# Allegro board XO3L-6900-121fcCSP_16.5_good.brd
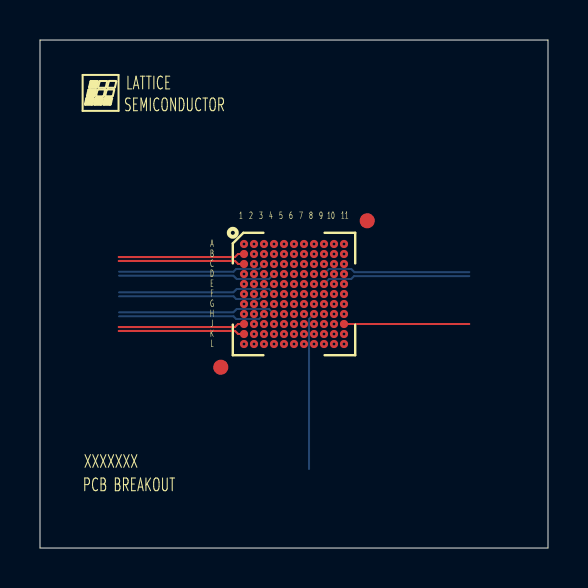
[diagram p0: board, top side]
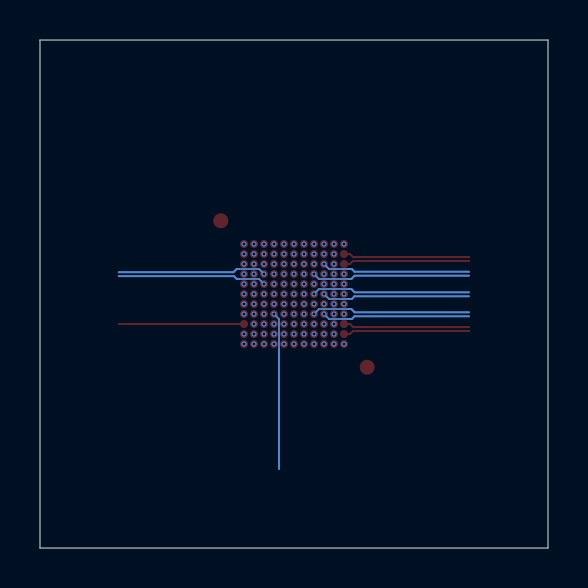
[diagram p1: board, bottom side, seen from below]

Outline 25.4 x 25.4 mm; copper layers: TOP, L2_GND, L3_SIGNAL1, L4_SIGNAL2, L5_PWR, BOTTOM. Coordinates in mm from the lower left corner of the outline.
Outline path: 0,25.4 25.4,25.4 25.4,0 0,0 0,25.4

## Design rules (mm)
net group CDPL10: nets PL10C PL10D
net group CDPT13: nets PT13C PT13D
net group CDPT15: nets PT15C PT15D
net group CDPT20: nets PT20C PT20D
net group CDPT23: nets PT23C PT23D
net group CDPT28: nets PT28C PT28D
net group PB3: nets PB3A PB3B
net group PB4: nets PB4A PB4B
net group PB7: nets PB7A PB7B
net group PB9: nets PB9A PB9B
net group PB10: nets PB10A PB10B
net group PB13: nets PB13A PB13B
net group PB20: nets PB20A PB20B
net group PB21: nets PB21A PB21B
net group PB24: nets PB24A PB24B
net group PB27: nets PB27A PB27B
net group PB29: nets PB29A PB29B
net group PB30: nets PB30A PB30B
net group PL3: nets PL3A PL3B
net group PL4: nets PL4A PL4B
net group PL6: nets PL6A PL6B
net group PL7: nets PL7A PL7B
net group PL8: nets PL8A PL8B
net group PL9: nets PL9A PL9B
net group PL14: nets PL14A PL14B
net group PL16: nets PL16A PL16B
net group PL17: nets PL17A PL17B
net group PL20: nets PL20A PL20B
net group PR2: nets PR2A PR2B
net group PR3: nets PR3A PR3B
net group PR5: nets PR5A PR5B
net group PR6: nets PR6A PR6B
net group PR8: nets PR8A PR8B
net group PR9: nets PR9A PR9B
net group PR10: nets PR10A PR10B
net group PR13: nets PR13A PR13B
net group PR14: nets PR14A PR14B
net group PR15: nets PR15A PR15B
net group PR16: nets PR16A PR16B
net group PR18: nets PR18A PR18B
net group PR19: nets PR19A PR19B
net group PT9: nets PT9A PT9B
net group PT11: nets PT11A PT11B
net group PT14: nets PT14A PT14B
net group PT18: nets PT18A PT18B
net group PT21: nets PT21A PT21B
net group PT24: nets PT24A PT24B
net group PT27: nets PT27A PT27B

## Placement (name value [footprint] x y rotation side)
BGA  -  [BGA121N50P11X11_600X600X100B-1]  12.7 12.7 270 top
NOREF  -  []  1.85 21.54 0 top

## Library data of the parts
BGA = BGA121N50P11X11_600X600X100B-1

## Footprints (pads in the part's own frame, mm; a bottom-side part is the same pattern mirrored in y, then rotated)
BGA121N50P11X11_600X600X100B-1
  round 0.75 smd: (-3.66,3.66) (3.66,-3.66)
  round 0.406 smd: A1(-2.5,-2.5) A2(-2.5,-2) A3(-2.5,-1.5) A4(-2.5,-1) A5(-2.5,-0.5) A6(-2.5,0) A7(-2.5,0.5) A8(-2.5,1) A9(-2.5,1.5) A10(-2.5,2) A11(-2.5,2.5) B1(-2,-2.5) B2(-2,-2) B3(-2,-1.5) B4(-2,-1) B5(-2,-0.5) B6(-2,0) B7(-2,0.5) B8(-2,1) B9(-2,1.5) B10(-2,2) B11(-2,2.5) C1(-1.5,-2.5) C2(-1.5,-2) C3(-1.5,-1.5) C4(-1.5,-1) C5(-1.5,-0.5) C6(-1.5,0) C7(-1.5,0.5) C8(-1.5,1) C9(-1.5,1.5) C10(-1.5,2) C11(-1.5,2.5) D1(-1,-2.5) D2(-1,-2) D3(-1,-1.5) D4(-1,-1) D5(-1,-0.5) D6(-1,0) D7(-1,0.5) D8(-1,1) D9(-1,1.5) D10(-1,2) D11(-1,2.5) E1(-0.5,-2.5) E2(-0.5,-2) E3(-0.5,-1.5) E4(-0.5,-1) E5(-0.5,-0.5) E6(-0.5,0) E7(-0.5,0.5) E8(-0.5,1) E9(-0.5,1.5) E10(-0.5,2) E11(-0.5,2.5) F1(0,-2.5) F2(0,-2) F3(0,-1.5) F4(0,-1) F5(0,-0.5) F6(0,0) F7(0,0.5) F8(0,1) F9(0,1.5) F10(0,2) F11(0,2.5) G1(0.5,-2.5) G2(0.5,-2) G3(0.5,-1.5) G4(0.5,-1) G5(0.5,-0.5) G6(0.5,0) G7(0.5,0.5) G8(0.5,1) G9(0.5,1.5) G10(0.5,2) G11(0.5,2.5) H1(1,-2.5) H2(1,-2) H3(1,-1.5) H4(1,-1) H5(1,-0.5) H6(1,0) H7(1,0.5) H8(1,1) H9(1,1.5) H10(1,2) H11(1,2.5) J1(1.5,-2.5) J2(1.5,-2) J3(1.5,-1.5) J4(1.5,-1) J5(1.5,-0.5) J6(1.5,0) J7(1.5,0.5) J8(1.5,1) J9(1.5,1.5) J10(1.5,2) J11(1.5,2.5) K1(2,-2.5) K2(2,-2) K3(2,-1.5) K4(2,-1) K5(2,-0.5) K6(2,0) K7(2,0.5) K8(2,1) K9(2,1.5) K10(2,2) K11(2,2.5) L1(2.5,-2.5) L2(2.5,-2) L3(2.5,-1.5) L4(2.5,-1) L5(2.5,-0.5) L6(2.5,0) L7(2.5,0.5) L8(2.5,1) L9(2.5,1.5) L10(2.5,2) L11(2.5,2.5)

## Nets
GND: BGA.A1 BGA.A11 BGA.E6 BGA.E7 BGA.F5 BGA.F6 BGA.G5 BGA.G6 BGA.L1 BGA.L11
VCC: BGA.D5 BGA.E5 BGA.F7 BGA.G7
VCCIO0: BGA.D6
VCCIO1: BGA.H5
VCCIO2: BGA.H6
VCCIO3: BGA.H8
VCCIO4: BGA.F8
VCCIO5: BGA.D8
PB3A: BGA.H9
PB3B: BGA.J9
PB4A: BGA.K10
PB4B: BGA.L10
PB7A: BGA.K9
PB7B: BGA.L9
PB9A: BGA.J8
PB9B: BGA.H7
PB10A: BGA.K8
PB10B: BGA.L8
PB13A: BGA.L7
PB13B: BGA.K7
PB15B: BGA.J7
PB20A: BGA.L6
PB20B: BGA.K6
PB21A: BGA.L5
PB21B: BGA.K5
PB23A: BGA.J6
PB24A: BGA.L4
PB24B: BGA.K4
PB27A: BGA.J5
PB27B: BGA.J4
PB29A: BGA.L3
PB29B: BGA.K3
PB30A: BGA.L2
PB30B: BGA.K2
PL3A: BGA.C9
PL3B: BGA.E8
PL4A: BGA.B10
PL4B: BGA.B11
PL6A: BGA.C10
PL6B: BGA.C11
PL7A: BGA.D9
PL7B: BGA.E9
PL8A: BGA.D10
PL8B: BGA.D11
PL9A: BGA.E10
PL9B: BGA.E11
PL10C: BGA.F11
PL10D: BGA.F10
PL13A: BGA.F9
PL14A: BGA.G11
PL14B: BGA.G10
PL16A: BGA.G9
PL16B: BGA.G8
PL17A: BGA.H11
PL17B: BGA.H10
PL19A: BGA.J11
PL20A: BGA.K11
PL20B: BGA.J10
PR2A: BGA.C2
PR2B: BGA.D3
PR3A: BGA.B1
PR3B: BGA.C1
PR5A: BGA.D2
PR5B: BGA.D1
PR6A: BGA.E4
PR6B: BGA.E3
PR8A: BGA.E2
PR8B: BGA.E1
PR9A: BGA.F3
PR9B: BGA.F4
PR10A: BGA.F2
PR10B: BGA.F1
PR13A: BGA.G1
PR13B: BGA.G2
PR14A: BGA.G3
PR14B: BGA.G4
PR15A: BGA.H1
PR15B: BGA.H2
PR16A: BGA.H3
PR16B: BGA.H4
PR18A: BGA.J1
PR18B: BGA.K1
PR19A: BGA.J2
PR19B: BGA.J3
PT9A: BGA.A10
PT9B: BGA.B9
PT10A: BGA.C8
PT11A: BGA.A9
PT11B: BGA.B8
PT13C: BGA.D7
PT13D: BGA.A8
PT14A: BGA.A7
PT14B: BGA.B7
PT15C: BGA.C7
PT15D: BGA.C6
PT18A: BGA.B6
PT18B: BGA.A6
PT20C: BGA.A5
PT20D: BGA.B5
PT21A: BGA.A4
PT21B: BGA.B4
PT23C: BGA.C5
PT23D: BGA.C4
PT24A: BGA.A3
PT24B: BGA.B3
PT27A: BGA.A2
PT27B: BGA.B2
PT28C: BGA.C3
PT28D: BGA.D4

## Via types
v1: diameter 0.254, hole 0.152, TOP to BOTTOM, 116 vias

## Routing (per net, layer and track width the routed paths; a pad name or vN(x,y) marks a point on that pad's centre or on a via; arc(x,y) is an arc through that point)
GND:
  vias: v1(10.2,15.2) v1(10.2,10.2) v1(12.2,12.7) v1(12.2,12.2) v1(12.7,13.2) v1(12.7,12.7) v1(12.7,12.2) v1(13.2,13.2) v1(15.2,15.2) v1(15.2,10.2)
VCC:
  vias: v1(12.2,13.7) v1(12.2,13.2) v1(13.2,12.7) v1(13.2,12.2)
VCCIO0:
  vias: v1(12.7,13.7)
VCCIO1:
  vias: v1(12.2,11.7)
VCCIO2:
  vias: v1(12.7,11.7)
VCCIO3: length 7.9
  BOTTOM w0.089: v1(13.7,11.7) 13.45,11.45 13.45,9.97
  BOTTOM w0.102: 13.45,3.95 13.45,9.97
VCCIO4:
  vias: v1(13.7,12.7)
VCCIO5:
  vias: v1(13.7,13.7)
PB3A: length 7.4
  L4_SIGNAL2 w0.089: 14.94,11.45 14.45,11.45 v1(14.2,11.7)
  L4_SIGNAL2 w0.102: 14.94,11.45 15.09,11.3 21.46,11.3
PB3B: length 7.4
  L4_SIGNAL2 w0.089: v1(14.2,11.2) 14.45,10.95 14.96,10.95
  L4_SIGNAL2 w0.102: 21.46,11.1 15.11,11.1 14.96,10.95
PB4A: length 6.9
  L3_SIGNAL1 w0.089: v1(14.7,10.7) 14.45,10.45 14.45,9.97
  L3_SIGNAL1 w0.102: 14.45,3.94 14.45,9.97
PB4B: length 6.3
  L3_SIGNAL1 w0.102: v1(14.7,10.2) 14.7,9.91 14.65,9.86 14.65,3.94
PB7A: length 6.9
  L3_SIGNAL1 w0.089: v1(14.2,10.7) 13.95,10.45 13.95,9.97
  L3_SIGNAL1 w0.102: 13.95,3.94 13.95,9.97
PB7B: length 6.3
  L3_SIGNAL1 w0.102: 14.15,3.94 14.15,9.86 14.2,9.91 v1(14.2,10.2)
PB9A: length 7.4
  L4_SIGNAL2 w0.089: v1(13.7,11.2) 13.95,10.95 13.95,9.98
  L4_SIGNAL2 w0.102: 13.95,9.98 13.95,9.86 13.79,9.7 13.79,3.94
PB9B: length 7.9
  L4_SIGNAL2 w0.089: 13.45,9.98 13.45,11.45 v1(13.2,11.7)
  L4_SIGNAL2 w0.102: 13.45,9.98 13.45,9.84 13.59,9.7 13.59,3.94
PB10A: length 6.9
  L3_SIGNAL1 w0.089: v1(13.7,10.7) 13.45,10.45 13.45,9.97
  L3_SIGNAL1 w0.102: 13.45,3.94 13.45,9.97
PB10B: length 6.3
  L3_SIGNAL1 w0.102: v1(13.7,10.2) 13.7,9.91 13.65,9.86 13.65,3.94
PB13A: length 6.3
  L3_SIGNAL1 w0.102: 13.15,3.94 13.15,9.86 13.2,9.91 v1(13.2,10.2)
PB13B: length 6.9
  L3_SIGNAL1 w0.089: 12.95,9.97 12.95,10.45 v1(13.2,10.7)
  L3_SIGNAL1 w0.102: 12.95,3.94 12.95,9.97
PB15B: length 7.4
  L4_SIGNAL2 w0.089: 12.95,9.98 12.95,10.95 v1(13.2,11.2)
  L4_SIGNAL2 w0.102: 12.95,3.94 12.95,9.98
PB20A: length 6.3
  L3_SIGNAL1 w0.102: 12.65,3.94 12.65,9.86 12.7,9.91 v1(12.7,10.2)
PB20B: length 6.9
  L3_SIGNAL1 w0.089: 12.45,9.97 12.45,10.45 v1(12.7,10.7)
  L3_SIGNAL1 w0.102: 12.45,3.94 12.45,9.97
PB21A: length 6.3
  L3_SIGNAL1 w0.102: 12.15,3.94 12.15,9.86 12.2,9.91 v1(12.2,10.2)
PB21B: length 6.9
  L3_SIGNAL1 w0.089: 11.95,9.97 11.95,10.45 v1(12.2,10.7)
  L3_SIGNAL1 w0.102: 11.95,3.94 11.95,9.97
PB23A: length 7.4
  L4_SIGNAL2 w0.089: 12.45,9.98 12.45,10.95 v1(12.7,11.2)
  L4_SIGNAL2 w0.102: 12.45,3.94 12.45,9.98
PB24A: length 6.3
  L3_SIGNAL1 w0.102: v1(11.7,10.2) 11.7,9.91 11.65,9.86 11.65,3.94
PB24B: length 6.9
  L3_SIGNAL1 w0.089: v1(11.7,10.7) 11.45,10.45 11.45,9.97
  L3_SIGNAL1 w0.102: 11.45,3.94 11.45,9.97
PB27A: length 7.4
  L4_SIGNAL2 w0.089: v1(12.2,11.2) 12.2,11.05 11.95,10.8 11.95,9.98
  L4_SIGNAL2 w0.102: 11.78,3.94 11.78,9.66 11.95,9.83 11.95,9.98
PB27B: length 7.4
  L4_SIGNAL2 w0.089: v1(11.7,11.2) 11.45,10.95 11.45,9.96
  L4_SIGNAL2 w0.102: 11.45,9.96 11.45,9.81 11.58,9.68 11.58,3.94
PB29A: length 6.3
  L3_SIGNAL1 w0.102: 11.15,3.94 11.15,9.86 11.2,9.91 v1(11.2,10.2)
PB29B: length 6.9
  L3_SIGNAL1 w0.089: v1(11.2,10.7) 10.95,10.45 10.95,9.97
  L3_SIGNAL1 w0.102: 10.95,3.94 10.95,9.97
PB30A: length 6.3
  L3_SIGNAL1 w0.102: 10.65,3.94 10.65,9.86 10.7,9.91 v1(10.7,10.2)
PB30B: length 6.9
  L3_SIGNAL1 w0.089: 10.45,9.97 10.45,10.45 v1(10.7,10.7)
  L3_SIGNAL1 w0.102: 10.45,3.94 10.45,9.97
PL3A: length 7.4
  L4_SIGNAL2 w0.089: v1(14.2,14.2) 14.45,14.45 14.45,15.42
  L4_SIGNAL2 w0.102: 14.45,15.42 14.45,15.57 14.3,15.72 14.3,21.46
PL3B: length 8.4
  L4_SIGNAL2 w0.089: 13.95,15.41 13.95,13.45 v1(13.7,13.2)
  L4_SIGNAL2 w0.102: 13.95,15.41 13.95,15.58 14.1,15.73 14.1,21.46
PL4A: length 6.9
  L3_SIGNAL1 w0.089: 15.43,14.95 14.95,14.95 v1(14.7,14.7)
  L3_SIGNAL1 w0.102: 21.46,14.95 15.43,14.95
PL4B: length 6.3
  L3_SIGNAL1 w0.102: v1(15.2,14.7) 15.49,14.7 15.54,14.75 21.46,14.75
PL6A: length 6.9
  L3_SIGNAL1 w0.089: v1(14.7,14.2) 14.95,14.45 15.43,14.45
  L3_SIGNAL1 w0.102: 21.46,14.45 15.43,14.45
PL6B: length 6.3
  L3_SIGNAL1 w0.102: 21.46,14.25 15.54,14.25 15.49,14.2 v1(15.2,14.2)
PL7A: length 7.4
  BOTTOM w0.089: 15.44,13.95 14.45,13.95 v1(14.2,13.7)
  BOTTOM w0.102: 15.44,13.95 15.56,13.95 15.72,13.79 21.46,13.79
PL7B: length 7.4
  BOTTOM w0.089: v1(14.2,13.2) 14.45,13.45 15.44,13.45
  BOTTOM w0.102: 21.46,13.59 15.7,13.59 15.56,13.45 15.44,13.45
PL8A: length 6.9
  L3_SIGNAL1 w0.089: 15.43,13.95 14.95,13.95 v1(14.7,13.7)
  L3_SIGNAL1 w0.102: 21.46,13.95 15.43,13.95
PL8B: length 6.3
  L3_SIGNAL1 w0.102: 21.46,13.75 15.54,13.75 15.49,13.7 v1(15.2,13.7)
PL9A: length 6.9
  L3_SIGNAL1 w0.089: 15.43,13.45 14.95,13.45 v1(14.7,13.2)
  L3_SIGNAL1 w0.102: 21.46,13.45 15.43,13.45
PL9B: length 6.3
  L3_SIGNAL1 w0.102: v1(15.2,13.2) 15.49,13.2 15.54,13.25 21.46,13.25
PL10C: length 6.3
  L3_SIGNAL1 w0.102: v1(15.2,12.7) 15.49,12.7 15.54,12.75 21.46,12.75
PL10D: length 6.9
  L3_SIGNAL1 w0.089: 15.43,12.95 14.95,12.95 v1(14.7,12.7)
  L3_SIGNAL1 w0.102: 21.46,12.95 15.43,12.95
PL13A: length 7.4
  L4_SIGNAL2 w0.089: v1(14.2,12.7) 14.45,12.95 15.44,12.95
  L4_SIGNAL2 w0.102: 21.46,12.95 15.44,12.95
PL14A: length 6.3
  L3_SIGNAL1 w0.102: 21.46,12.25 15.54,12.25 15.49,12.2 v1(15.2,12.2)
PL14B: length 6.9
  L3_SIGNAL1 w0.089: v1(14.7,12.2) 14.95,12.45 15.43,12.45
  L3_SIGNAL1 w0.102: 21.46,12.45 15.43,12.45
PL16A: length 7.4
  L4_SIGNAL2 w0.089: 15.44,11.95 14.45,11.95 v1(14.2,12.2)
  L4_SIGNAL2 w0.102: 21.46,12.1 15.67,12.1 15.52,11.95 15.44,11.95
PL16B: length 7.9
  L4_SIGNAL2 w0.089: v1(13.7,12.2) 13.95,12.45 15.42,12.45
  L4_SIGNAL2 w0.102: 15.42,12.45 15.56,12.45 15.71,12.3 21.46,12.3
PL17A: length 6.3
  L3_SIGNAL1 w0.102: 21.46,11.75 15.54,11.75 15.49,11.7 v1(15.2,11.7)
PL17B: length 6.9
  L3_SIGNAL1 w0.089: 15.43,11.95 14.95,11.95 v1(14.7,11.7)
  L3_SIGNAL1 w0.102: 21.46,11.95 15.43,11.95
PL19A: length 6.3
  TOP w0.102: 21.46,11.2 BGA.J11
PL20A: length 6.7
  L3_SIGNAL1 w0.102: v1(15.2,10.7) 15.09,10.81 15.09,10.95 15.2,11.05 21.46,11.05
PL20B: length 6.9
  L3_SIGNAL1 w0.102: 21.46,11.25 15.11,11.25 14.95,11.09 14.81,11.09 v1(14.7,11.2)
PR2A: length 6.8
  L4_SIGNAL2 w0.102: 3.94,14.15 10.03,14.15 10.08,14.2 v1(10.7,14.2)
PR2B: length 7.4
  L4_SIGNAL2 w0.089: v1(11.2,13.7) 10.95,13.95 9.98,13.95
  L4_SIGNAL2 w0.102: 3.94,13.95 9.98,13.95
PR3A: length 6.3
  TOP w0.102: 3.94,14.55 9.75,14.55 9.9,14.7 BGA.B1
PR3B: length 6.3
  TOP w0.102: 3.94,14.35 9.75,14.35 9.9,14.2 BGA.C1
PR5A: length 6.9
  L3_SIGNAL1 w0.089: v1(10.7,13.7) 10.45,13.95 9.97,13.95
  L3_SIGNAL1 w0.102: 3.94,13.95 9.97,13.95
PR5B: length 6.3
  L3_SIGNAL1 w0.102: 3.94,13.75 9.86,13.75 9.91,13.7 v1(10.2,13.7)
PR6A: length 7.9
  L4_SIGNAL2 w0.089: 10.01,12.95 11.45,12.95 v1(11.7,13.2)
  L4_SIGNAL2 w0.102: 3.94,13.11 9.73,13.11 9.88,12.95 10.01,12.95
PR6B: length 7.4
  L4_SIGNAL2 w0.089: v1(11.2,13.2) 10.95,13.45 9.98,13.45
  L4_SIGNAL2 w0.102: 3.94,13.3 9.72,13.3 9.87,13.45 9.98,13.45
PR8A: length 6.9
  L3_SIGNAL1 w0.089: v1(10.7,13.2) 10.45,13.45 9.97,13.45
  L3_SIGNAL1 w0.102: 3.94,13.45 9.97,13.45
PR8B: length 6.3
  L3_SIGNAL1 w0.102: 3.94,13.25 9.86,13.25 9.91,13.2 v1(10.2,13.2)
PR9A: length 7.4
  BOTTOM w0.089: 10.01,12.45 10.95,12.45 v1(11.2,12.7)
  BOTTOM w0.102: 10.01,12.45 9.81,12.45 9.67,12.59 3.95,12.59
PR9B: length 7.9
  BOTTOM w0.089: 9.97,12.95 11.45,12.95 v1(11.7,12.7)
  BOTTOM w0.102: 9.97,12.95 9.83,12.95 9.67,12.79 3.95,12.79
PR10A: length 6.9
  L3_SIGNAL1 w0.089: v1(10.7,12.7) 10.45,12.95 9.97,12.95
  L3_SIGNAL1 w0.102: 3.94,12.95 9.97,12.95
PR10B: length 6.3
  L3_SIGNAL1 w0.102: 3.94,12.75 9.86,12.75 9.91,12.7 v1(10.2,12.7)
PR13A: length 6.3
  L3_SIGNAL1 w0.102: 3.94,12.25 9.86,12.25 9.91,12.2 v1(10.2,12.2)
PR13B: length 6.9
  L3_SIGNAL1 w0.089: 9.97,12.45 10.45,12.45 v1(10.7,12.2)
  L3_SIGNAL1 w0.102: 3.94,12.45 9.97,12.45
PR14A: length 7.4
  L4_SIGNAL2 w0.089: v1(11.2,12.2) 10.95,12.45 9.98,12.45
  L4_SIGNAL2 w0.102: 9.98,12.45 9.87,12.45 9.72,12.3 3.94,12.3
PR14B: length 7.9
  L4_SIGNAL2 w0.089: v1(11.7,12.2) 11.45,11.95 10.01,11.95
  L4_SIGNAL2 w0.102: 3.94,12.11 9.73,12.11 9.88,11.95 10.01,11.95
PR15A: length 6.3
  L3_SIGNAL1 w0.102: v1(10.2,11.7) 9.91,11.7 9.86,11.75 3.94,11.75
PR15B: length 6.9
  L3_SIGNAL1 w0.089: 9.97,11.95 10.45,11.95 v1(10.7,11.7)
  L3_SIGNAL1 w0.102: 3.94,11.95 9.97,11.95
PR16A: length 7.4
  BOTTOM w0.089: v1(11.2,11.7) 10.95,11.45 10.01,11.45
  BOTTOM w0.102: 3.95,11.59 9.67,11.59 9.81,11.45 10.01,11.45
PR16B: length 7.9
  BOTTOM w0.089: v1(11.7,11.7) 11.45,11.95 9.97,11.95
  BOTTOM w0.102: 3.95,11.79 9.67,11.79 9.83,11.95 9.97,11.95
PR18A: length 6.3
  TOP w0.102: BGA.J1 9.9,11.2 9.75,11.05 3.94,11.05
PR18B: length 6.3
  TOP w0.102: BGA.K1 9.9,10.7 9.75,10.85 3.94,10.85
PR19A: length 6.8
  L4_SIGNAL2 w0.102: v1(10.7,11.2) 10.03,11.2 9.98,11.15 3.94,11.15
PR19B: length 7.4
  L4_SIGNAL2 w0.089: 10.36,10.95 10.95,10.95 v1(11.2,11.2)
  L4_SIGNAL2 w0.102: 3.94,10.95 10.36,10.95
PT9A: length 6.3
  L3_SIGNAL1 w0.102: v1(14.7,15.2) 14.7,15.49 14.65,15.55 14.65,21.46
PT9B: length 6.9
  L3_SIGNAL1 w0.089: v1(14.2,14.7) 14.45,14.95 14.45,15.43
  L3_SIGNAL1 w0.102: 14.45,15.43 14.45,21.46
PT10A: length 7.4
  L4_SIGNAL2 w0.089: 13.45,15.43 13.45,14.45 v1(13.7,14.2)
  L4_SIGNAL2 w0.102: 13.45,15.43 13.45,21.48
PT11A: length 6.3
  L3_SIGNAL1 w0.102: v1(14.2,15.2) 14.2,15.49 14.15,15.55 14.15,21.46
PT11B: length 6.9
  L3_SIGNAL1 w0.089: v1(13.7,14.7) 13.95,14.95 13.95,15.43
  L3_SIGNAL1 w0.102: 13.95,15.43 13.95,21.46
PT13C: length 7.9
  L3_SIGNAL1 w0.089: v1(13.2,13.7) 13.45,13.95 13.45,15.49
  L3_SIGNAL1 w0.102: 13.45,15.49 13.45,21.46
PT13D: length 6.3
  L3_SIGNAL1 w0.102: 13.65,21.46 13.65,15.54 13.7,15.49 v1(13.7,15.2)
PT14A: length 6.3
  L3_SIGNAL1 w0.102: 13.15,21.46 13.15,15.54 13.2,15.49 v1(13.2,15.2)
PT14B: length 6.9
  L3_SIGNAL1 w0.089: 12.95,15.43 12.95,14.95 v1(13.2,14.7)
  L3_SIGNAL1 w0.102: 12.95,21.46 12.95,15.43
PT15C: length 7.4
  L4_SIGNAL2 w0.089: 12.95,15.42 12.95,14.45 v1(13.2,14.2)
  L4_SIGNAL2 w0.102: 12.8,21.46 12.8,15.72 12.95,15.57 12.95,15.42
PT15D: length 7.4
  L4_SIGNAL2 w0.089: 12.45,15.42 12.45,14.45 v1(12.7,14.2)
  L4_SIGNAL2 w0.102: 12.6,21.46 12.6,15.73 12.45,15.57 12.45,15.42
PT18A: length 6.9
  L3_SIGNAL1 w0.089: v1(12.7,14.7) 12.45,14.95 12.45,15.43
  L3_SIGNAL1 w0.102: 12.45,21.46 12.45,15.43
PT18B: length 6.3
  L3_SIGNAL1 w0.102: 12.65,21.46 12.65,15.54 12.7,15.49 v1(12.7,15.2)
PT20C: length 6.3
  L3_SIGNAL1 w0.102: 12.15,21.46 12.15,15.54 12.2,15.49 v1(12.2,15.2)
PT20D: length 6.9
  L3_SIGNAL1 w0.089: 11.95,15.43 11.95,14.95 v1(12.2,14.7)
  L3_SIGNAL1 w0.102: 11.95,21.46 11.95,15.43
PT21A: length 6.3
  L3_SIGNAL1 w0.102: v1(11.7,15.2) 11.7,15.49 11.65,15.54 11.65,21.46
PT21B: length 6.9
  L3_SIGNAL1 w0.089: 11.45,15.43 11.45,14.95 v1(11.7,14.7)
  L3_SIGNAL1 w0.102: 11.45,21.46 11.45,15.43
PT23C: length 7.4
  L4_SIGNAL2 w0.089: v1(12.2,14.2) 11.95,14.45 11.95,15.42
  L4_SIGNAL2 w0.102: 11.8,21.46 11.8,15.72 11.95,15.57 11.95,15.42
PT23D: length 7.4
  L4_SIGNAL2 w0.089: 11.45,15.42 11.45,14.45 v1(11.7,14.2)
  L4_SIGNAL2 w0.102: 11.6,21.46 11.6,15.73 11.45,15.57 11.45,15.42
PT24A: length 6.3
  L3_SIGNAL1 w0.102: v1(11.2,15.2) 11.2,15.49 11.15,15.54 11.15,21.46
PT24B: length 6.9
  L3_SIGNAL1 w0.089: v1(11.2,14.7) 10.95,14.95 10.95,15.43
  L3_SIGNAL1 w0.102: 10.95,21.46 10.95,15.43
PT27A: length 6.3
  L3_SIGNAL1 w0.102: 10.65,21.46 10.65,15.54 10.7,15.49 v1(10.7,15.2)
PT27B: length 6.9
  L3_SIGNAL1 w0.089: v1(10.7,14.7) 10.45,14.95 10.45,15.43
  L3_SIGNAL1 w0.102: 10.45,21.46 10.45,15.43
PT28C: length 7.4
  BOTTOM w0.089: 10.01,13.95 10.95,13.95 v1(11.2,14.2)
  BOTTOM w0.102: 10.01,13.95 9.81,13.95 9.67,13.81 3.95,13.81
PT28D: length 7.9
  BOTTOM w0.089: v1(11.7,13.7) 11.45,13.45 9.97,13.45
  BOTTOM w0.102: 9.97,13.45 9.83,13.45 9.67,13.61 3.95,13.61

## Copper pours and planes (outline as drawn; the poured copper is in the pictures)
GND on L2_GND: 1.27,1.27 1.27,24.13 24.13,24.13 24.13,1.27
VCC on L5_PWR: 1.32,12.04 1.32,24.1 9.98,24.1 9.98,16.28 12.37,13.89 12.37,13.11 13.36,13.11 13.36,12.04
VCCIO0 on L5_PWR: 12.52,13.28 12.52,14.02 10.16,16.38 10.16,24.1 21.39,24.1 13.61,16.33 13.61,14.22 13.11,13.72 13.11,13.28
VCCIO1 on L5_PWR: 12.37,11.86 12.37,1.3 1.3,1.3 1.3,11.86
VCCIO2 on L5_PWR: 12.55,11.86 12.55,1.3 24.1,1.3 24.1,4.83 20.47,4.83 13.44,11.86
VCCIO4 on L5_PWR: 13.54,13.11 13.54,12.04 20.55,5.03 24.1,5.03 24.1,13.11
VCCIO5 on L5_PWR: 13.28,13.28 13.28,13.67 13.79,14.17 13.79,16.26 21.64,24.1 24.1,24.1 24.1,13.28

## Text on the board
User.Comments: R.P | REN | 09/05/14 | DWG NO: | XXXX-##XXXXX | REVISION | 1.0 | SHEET | 1 | OF | LATTICE SEMICONDUCTOR CORPORATION | DESCRIPTION
Ref Des/Silkscreen Top: A | B | C | D | E | F | G | H | J | K | L | 1 | 2 | 3 | 4 | 5 | 6 | 7 | 8 | 9 | 10 | 11 | PCB BREAKOUT | XXXXXXX | SEMICONDUCTOR | LATTICE
PAGE_OUTLINE: SPECIAL INSTRUCTIONS: | LIKE VIA FILL | SPECIFY ANY SPECIAL INSTRUCTIONS | GND     PLANE  (L2) | TOP SIDE       (L1) | SIGNAL2        (L4) | POWER   PLANE  (L5) | SIGNAL1        (L3) | BOTTOM SIDE    (L6) | BOTTOM SILKSCREEN | TOP SOLDERMASK | BOTTOM SOLDERMASK | TOP SILKSCREEN | DESIGNED BY: | APPROVED BY: | SIGNATURES         DATE | REV | 1 | INITIAL RELEASE | ESCAPE VIA DRILL | TRACE WIDTH/SPACE | ESCAPE VIA PAD | LAND OPENING | PACKAGE SIZE | LAND PAD | PITCH | DESCRIPTION | 0.102/0.097 | 0.1524 | 0.254 | 6 x 6 | 0.4064 | 0.50 | MM | MM/DD/YYYY | DATE | 236.2x236.2 | 4.00/3.80 | 10.00 | 16.00 | 6.00 | 19.69 | MILS | APPEOVED | X. XXXXX | 4 LAYER STACKUP | PCB BREAKOUT DETAILS | REVISION
PLACE_BOUND_TOP: FIGURE | SIZE | 6.0 | DRILL CHART: TOP to BOTTOM | ALL UNITS ARE IN MILS | PLATED | QTY | 121
